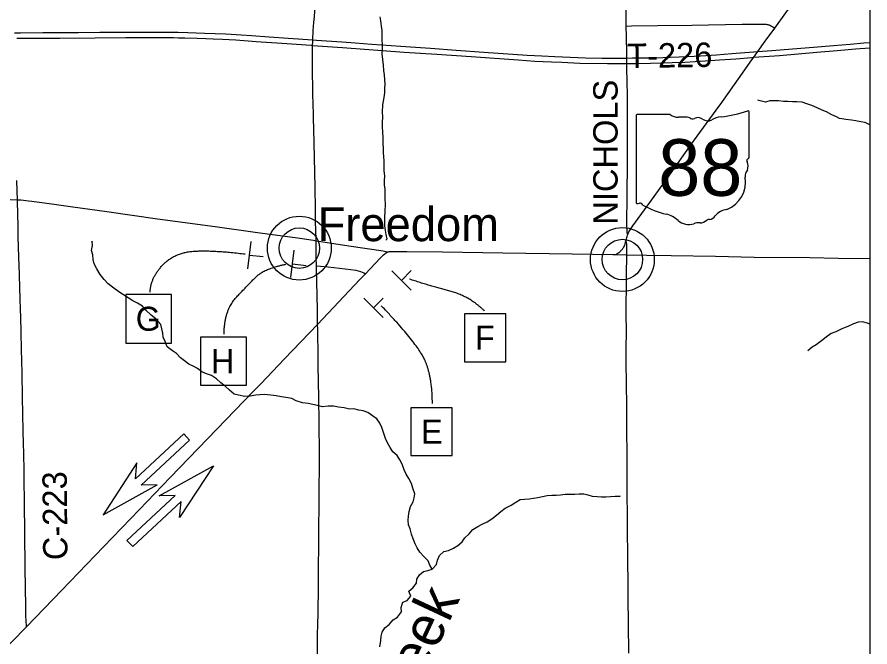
# Model space of a CAD drawing. Extents: x 0 to 34, y 0 to 22.
# Drawn here: x 13.701 to 18.671, y 14.409 to 18.077 of the extents above; entities that cross this region are included whole.
import ezdxf

# ---------------------------------------------------------------- set-up
doc = ezdxf.new("R2010")
doc.units = 0
for name, color, linetype in [('GM_X_County_Road', 7, 'Continuous'), ('GM_X_County_Road_Text', 7, 'Continuous'), ('GM_X_Interstate_Route', 7, 'Continuous'), ('GM_X_Minor_River', 7, 'Continuous'), ('GM_X_Minor_River_Text', 7, 'Continuous'), ('GM_X_State_Location', 7, 'Continuous'), ('GM_X_State_Route', 7, 'Continuous'), ('GM_X_State_Shield', 7, 'Continuous'), ('GM_X_Township_Road', 7, 'Continuous'), ('GM_X_Township_Road_Text', 7, 'Continuous'), ('GM_X_Unincorporated', 7, 'Continuous'), ('GM_X_Unincorporated_Location', 7, 'Continuous'), ('GM_X_Unincorporated_Text', 7, 'Continuous'), ('PM_P_Cells', 7, 'Continuous'), ('SH_Text', 7, 'Continuous'), ('SN_P_Signs', 7, 'Continuous')]:
    doc.layers.add(name, color=color, linetype=linetype)

msp = doc.modelspace()

# ---------------------------------------------------------------- linework, layer by layer
at = {"layer": 'GM_X_County_Road'}
for points in [[(17.2512, 18.0254), (17.2505, 18.0622), (17.2503, 18.1617)], [(17.2605, 16.8112), (17.2591, 16.8136), (17.258, 16.8161), (17.2571, 16.8198), (17.2565, 16.8243), (17.2557, 16.8355), (17.2554, 16.8677), (17.2554, 16.9284), (17.256, 16.9826), (17.2567, 17.0541), (17.2569, 17.1007), (17.2577, 17.1691), (17.2583, 17.2406), (17.2582, 17.3074), (17.259, 17.382), (17.2585, 17.4737), (17.258, 17.5545), (17.2574, 17.6089), (17.256, 17.7143), (17.2554, 17.7656), (17.2551, 17.8077), (17.2545, 17.8386), (17.2541, 17.8604), (17.2519, 17.9706), (17.2513, 18.0188), (17.2512, 18.0254)], [(13.7026, 17.0131), (13.7009, 17.0659), (13.6992, 17.1249)], [(13.7555, 14.5258), (13.7539, 14.5643), (13.7529, 14.5876), (13.7515, 14.6529), (13.7505, 14.7477), (13.7483, 14.8782), (13.748, 14.9419), (13.747, 15.0009), (13.746, 15.0987), (13.7441, 15.2214), (13.7437, 15.2789), (13.7422, 15.3565), (13.7414, 15.4342), (13.7394, 15.5351), (13.7383, 15.5942), (13.7367, 15.6656), (13.7347, 15.7666), (13.7329, 15.8629), (13.7297, 16.0027), (13.7271, 16.144), (13.7251, 16.2397), (13.7221, 16.3314), (13.7209, 16.3733), (13.7186, 16.4385), (13.7168, 16.4991), (13.7152, 16.5798), (13.7113, 16.6792), (13.708, 16.7973), (13.7067, 16.8703), (13.7047, 16.9215), (13.7026, 17.0131)], [(17.2492, 16.7724), (17.2511, 16.779), (17.2548, 16.793), (17.2569, 16.8003), (17.2592, 16.8077), (17.2605, 16.8112)], [(17.2539, 16.6935), (17.2541, 16.7174), (17.254, 16.7445), (17.2536, 16.7571), (17.2532, 16.7615), (17.2521, 16.7658), (17.2508, 16.7694), (17.2492, 16.7724)], [(17.2662, 14.3722), (17.2658, 14.4187), (17.2654, 14.4436), (17.265, 14.4747), (17.2651, 14.5197), (17.2638, 14.5895), (17.2637, 14.6003), (17.2631, 14.6407), (17.2626, 14.6794), (17.2618, 14.7166), (17.2614, 14.7599), (17.2615, 14.8277), (17.2612, 14.8649), (17.2609, 14.8913), (17.26, 14.9876), (17.259, 15.042), (17.2586, 15.0683), (17.2584, 15.1428), (17.2581, 15.1909), (17.2576, 15.2142), (17.2572, 15.2593), (17.2569, 15.3386), (17.2562, 15.4147), (17.2556, 15.4691), (17.2555, 15.5561), (17.255, 15.6447), (17.255, 15.7037), (17.2547, 15.7457), (17.2545, 15.8234), (17.2527, 15.932), (17.2518, 15.994), (17.2515, 16.0174), (17.2515, 16.0809), (17.2514, 16.1628), (17.2524, 16.23), (17.2511, 16.3648), (17.2511, 16.4067), (17.2521, 16.5), (17.2522, 16.5497), (17.2523, 16.6057), (17.2535, 16.6614), (17.2535, 16.6749), (17.2539, 16.6935)], [(15.4512, 14.3501), (15.4524, 14.4268), (15.4525, 14.4802), (15.4545, 14.5423), (15.456, 14.6012), (15.4564, 14.6587), (15.4566, 14.7099), (15.4571, 14.7783), (15.4581, 14.8264), (15.4585, 14.9056), (15.459, 14.9662), (15.4594, 14.9926), (15.4604, 15.0577), (15.4604, 15.0965), (15.4602, 15.1183), (15.4618, 15.2146), (15.4619, 15.269), (15.4621, 15.3218), (15.4624, 15.3545), (15.4629, 15.4336), (15.4634, 15.4771), (15.4636, 15.5376), (15.4632, 15.592), (15.4623, 15.6588), (15.4612, 15.7131), (15.4605, 15.7597), (15.4599, 15.8172), (15.4587, 15.8855), (15.4579, 15.9306), (15.457, 15.9694), (15.4565, 16.0331), (15.4555, 16.1201), (15.454, 16.233), (15.4532, 16.2601), (15.4521, 16.2873)]]:
    msp.add_lwpolyline(points, dxfattribs=at)
at = {"layer": 'GM_X_Interstate_Route'}
for points in [[(13.6852, 17.9863), (13.7215, 17.9865), (13.8507, 17.9874), (13.985, 17.9878), (14.0594, 17.9882), (14.1831, 17.9889), (14.3769, 17.9902), (14.4288, 17.9905), (14.4793, 17.9905), (14.5667, 17.99), (14.6399, 17.9887), (14.6967, 17.9876), (14.7928, 17.9844), (14.8558, 17.9821), (14.9156, 17.9792), (14.9495, 17.9772), (15.0062, 17.974), (15.0676, 17.9693), (15.1701, 17.9621), (15.2812, 17.9544), (15.4244, 17.9442), (15.4457, 17.9427), (15.5926, 17.9324), (15.6717, 17.9268), (15.7679, 17.9201), (15.9372, 17.9083), (16.0219, 17.9024), (16.1109, 17.8963), (16.2594, 17.8856), (16.4212, 17.8737), (16.6732, 17.8562), (16.7592, 17.8512), (16.8351, 17.8475), (16.9245, 17.843), (17.0131, 17.8403), (17.1084, 17.8386), (17.2258, 17.8382), (17.2545, 17.8386), (17.288, 17.8392), (17.3585, 17.8394), (17.4211, 17.8408), (17.5066, 17.8435), (17.5601, 17.8455), (17.6106, 17.8474), (17.6831, 17.8521), (17.7776, 17.8584), (17.8666, 17.865), (18.0187, 17.877), (18.0986, 17.8832), (18.3656, 17.9041), (18.4593, 17.9122), (18.5569, 17.9205), (18.635, 17.9268), (18.6712, 17.9296)], [(13.7002, 17.9542), (13.8218, 17.9548), (13.9505, 17.9554), (14.1551, 17.9566), (14.3339, 17.9577), (14.4149, 17.958), (14.6123, 17.9579), (14.6418, 17.9571), (14.6777, 17.9563), (14.7508, 17.9542), (14.8016, 17.9526), (14.8432, 17.9509), (14.8989, 17.9485), (14.9751, 17.944), (15.0937, 17.9355), (15.2443, 17.9247), (15.4155, 17.9131)], [(15.4155, 17.9131), (15.4231, 17.9126), (15.597, 17.9009), (15.9577, 17.874), (16.1462, 17.8611), (16.348, 17.8476), (16.622, 17.8281), (16.7181, 17.8216), (16.8149, 17.8161), (16.8751, 17.8139), (16.9808, 17.8098), (17.1422, 17.8073), (17.2375, 17.8076), (17.2551, 17.8077), (17.3226, 17.808), (17.4627, 17.8113), (17.5192, 17.8127), (17.5926, 17.8154), (17.6519, 17.8188), (17.71, 17.8221), (17.7947, 17.8277), (17.8896, 17.8351), (17.9818, 17.8421)], [(17.9818, 17.8421), (17.9942, 17.843), (18.1435, 17.8543), (18.3622, 17.8736), (18.481, 17.8831), (18.5867, 17.8916), (18.6712, 17.8983)]]:
    msp.add_lwpolyline(points, dxfattribs=at)
at = {"layer": 'GM_X_Minor_River'}
for points in [[(15.8152, 18.0783), (15.8183, 18.0546), (15.8224, 18.0252), (15.8265, 17.9996), (15.8258, 17.9721), (15.8261, 17.9455), (15.8293, 17.918), (15.8286, 17.8943), (15.8261, 17.8639), (15.8312, 17.8297), (15.8335, 17.7975), (15.8357, 17.7671), (15.8407, 17.7406), (15.842, 17.7121), (15.8432, 17.6865), (15.8425, 17.6618), (15.8428, 17.6362), (15.8374, 17.6086), (15.8303, 17.5658), (15.8289, 17.5231), (15.8302, 17.4955), (15.8286, 17.4632), (15.828, 17.4376), (15.8311, 17.4073), (15.8334, 17.374), (15.8328, 17.3389), (15.8341, 17.3133), (15.8353, 17.2886), (15.8356, 17.2639), (15.8377, 17.2393), (15.839, 17.2146), (15.8374, 17.1823), (15.8425, 17.152), (15.84, 17.1244), (15.8412, 17.0998), (15.8433, 17.0751), (15.8436, 17.0485), (15.8449, 17.0191), (15.8462, 16.9887), (15.8438, 16.945), (15.8423, 16.9118), (15.8416, 16.888), (15.8419, 16.8624), (15.846, 16.8349), (15.8491, 16.8112), (15.8551, 16.7847), (15.8504, 16.779)], [(18.4757, 17.4968), (18.45, 17.5088), (18.4186, 17.5246), (18.3929, 17.5348), (18.3634, 17.5487), (18.3329, 17.5616), (18.3035, 17.5727), (18.2759, 17.5809), (18.2456, 17.5843), (18.22, 17.584), (18.1935, 17.5866), (18.167, 17.5863), (18.1385, 17.5897), (18.0874, 17.5891), (18.0629, 17.5822), (18.0315, 17.5894), (18.0173, 17.594)], [(18.6436, 17.4634), (18.6189, 17.4669), (18.5894, 17.4723), (18.5628, 17.4768), (18.5314, 17.4812), (18.5075, 17.4842), (18.4932, 17.4869), (18.4757, 17.4968)], [(18.6712, 17.4496), (18.6703, 17.4503), (18.6436, 17.4634)], [(14.1407, 16.7468), (14.1386, 16.7714), (14.1386, 16.7695)], [(16.1207, 14.8614), (16.1062, 14.8859), (16.0964, 14.9115), (16.0725, 14.934), (16.0486, 14.9603), (16.0322, 14.9857), (16.0205, 15.0103), (16.0098, 15.0396), (16, 15.066), (15.9921, 15.0963), (15.9814, 15.1209), (15.9793, 15.1465), (15.9818, 15.1712), (15.9853, 15.1978), (15.9935, 15.2274), (16.0084, 15.2541), (16.0147, 15.2779), (16.0183, 15.3017), (16.0065, 15.3339), (15.9996, 15.3604), (15.9832, 15.3896), (15.9687, 15.4151), (15.9561, 15.4406), (15.9444, 15.4727), (15.9318, 15.4991), (15.9154, 15.5236), (15.8915, 15.5452), (15.8752, 15.5706), (15.8597, 15.597), (15.8471, 15.6235), (15.8392, 15.6519), (15.8265, 15.6878), (15.8158, 15.7124), (15.7976, 15.7378), (15.7718, 15.7555), (15.746, 15.7742), (15.7185, 15.7834), (15.6928, 15.7878), (15.6625, 15.7951), (15.6379, 15.7938), (15.6065, 15.8011), (15.5743, 15.8064), (15.5458, 15.8108), (15.5146, 15.8105), (15.4805, 15.8072), (15.452, 15.8154), (15.4245, 15.8218), (15.3979, 15.8271), (15.3648, 15.8315), (15.3277, 15.8434), (15.3029, 15.8555), (15.2783, 15.859), (15.2422, 15.8662), (15.21, 15.8715), (15.1806, 15.8759), (15.1408, 15.8802), (15.1162, 15.878), (15.0916, 15.8748), (15.0585, 15.8688), (15.0292, 15.8684), (14.9922, 15.8746), (14.9656, 15.8819), (14.9398, 15.9044), (14.9139, 15.9288), (14.8882, 15.9465), (14.8623, 15.9709), (14.8347, 15.9896), (14.8052, 15.9997), (14.7776, 16.0117), (14.7518, 16.0304), (14.727, 16.0453), (14.7014, 16.0564), (14.6775, 16.0751), (14.6526, 16.0938), (14.6306, 16.1182), (14.6058, 16.1331), (14.5762, 16.1575), (14.5635, 16.1887), (14.5529, 16.2132), (14.5498, 16.2369), (14.5447, 16.2616), (14.5378, 16.2862), (14.5091, 16.32), (14.4823, 16.3406), (14.4508, 16.3696), (14.4315, 16.3941), (14.403, 16.4109), (14.3753, 16.4248), (14.3486, 16.4425), (14.321, 16.4593), (14.2943, 16.477), (14.2656, 16.4985), (14.2322, 16.5247), (14.2083, 16.5482), (14.1852, 16.5773), (14.165, 16.6103), (14.1495, 16.6396), (14.1435, 16.6651), (14.1432, 16.6927), (14.1354, 16.7173), (14.1407, 16.7468)], [(18.5068, 16.2626), (18.4715, 16.2445), (18.4451, 16.2347), (18.416, 16.2125), (18.3898, 16.1913), (18.3588, 16.1691), (18.3343, 16.1555), (18.309, 16.1334), (18.3099, 16.1334)], [(18.6712, 16.2887), (18.6574, 16.2945), (18.6269, 16.3018), (18.6032, 16.3006), (18.5749, 16.2908), (18.5427, 16.2762), (18.5172, 16.2665), (18.5068, 16.2626)], [(15.8151, 14.4088), (15.8204, 14.4459), (15.822, 14.4716), (15.8293, 14.4954), (15.8442, 14.5202), (15.8686, 14.5404), (15.8919, 14.5673), (15.9183, 14.5828), (15.9407, 14.6134), (15.9395, 14.6381), (15.9486, 14.6695), (15.974, 14.6803), (15.9955, 14.7043), (15.9838, 14.7336), (16.0082, 14.7528), (16.0288, 14.7806), (16.0313, 14.8044), (16.0453, 14.8283), (16.0697, 14.8485), (16.0952, 14.8545), (16.1207, 14.8614), (16.145, 14.8883), (16.1513, 14.914), (16.1624, 14.9426), (16.1877, 14.9647), (16.216, 14.9708), (16.2452, 14.9844), (16.2697, 15.0008), (16.2941, 15.021), (16.3108, 15.045), (16.3362, 15.0681), (16.3576, 15.0939), (16.3859, 15.1114), (16.4122, 15.125), (16.4414, 15.1386), (16.4677, 15.156), (16.494, 15.1772), (16.5203, 15.1974), (16.5447, 15.2176), (16.5805, 15.2351), (16.6068, 15.2525), (16.6331, 15.268), (16.6587, 15.2702), (16.6852, 15.2715), (16.7098, 15.2756), (16.7362, 15.2797), (16.7636, 15.2847), (16.7901, 15.2907), (16.8175, 15.293), (16.8421, 15.2932), (16.8677, 15.2945), (16.8951, 15.2986), (16.9509, 15.2993), (16.9774, 15.3015), (17.003, 15.3008), (17.0267, 15.2944), (17.0533, 15.2871), (17.0808, 15.2846), (17.1064, 15.283), (17.1329, 15.2833), (17.1585, 15.2846), (17.1868, 15.2877), (17.2134, 15.2871), (17.2171, 15.289)]]:
    msp.add_lwpolyline(points, dxfattribs=at)
at = {"layer": 'GM_X_State_Route'}
for points in [[(15.4253, 17.6106), (15.4249, 17.6255), (15.4244, 17.6845), (15.4231, 17.7357), (15.4222, 17.7932), (15.4218, 17.8414), (15.4221, 17.885), (15.4231, 17.9126), (15.4238, 17.9332), (15.4244, 17.9442), (15.4272, 18), (15.4305, 18.0465), (15.4338, 18.0806), (15.437, 18.1115), (15.4405, 18.1471), (15.4466, 18.198), (15.4511, 18.2303), (15.4581, 18.2764), (15.4671, 18.338), (15.4675, 18.3404)], [(17.9736, 17.8144), (17.9942, 17.843), (18.0187, 17.877), (18.0616, 17.9363), (18.1166, 18.0127), (18.1805, 18.1014), (18.2511, 18.1988)], [(17.7976, 17.5666), (17.9278, 17.7511), (17.9736, 17.8144)], [(15.4521, 16.2873), (15.4519, 16.3052), (15.451, 16.3857), (15.449, 16.4416), (15.4472, 16.5489), (15.4459, 16.597), (15.4452, 16.6282), (15.4441, 16.6794), (15.4432, 16.7751), (15.4418, 16.8425), (15.4406, 16.8782), (15.44, 16.9559), (15.4372, 17.088), (15.4363, 17.172), (15.4317, 17.3443), (15.4278, 17.4941), (15.4259, 17.5882), (15.4253, 17.6106)], [(17.2605, 16.8112), (17.2625, 16.8162), (17.2647, 16.8211), (17.267, 16.8259), (17.2704, 16.832), (17.2739, 16.8378), (17.2902, 16.8623), (17.372, 16.9757), (17.4893, 17.1382), (17.6439, 17.3544), (17.7961, 17.5646), (17.7976, 17.5666)], [(13.6208, 17.016), (13.7026, 17.0131), (13.7234, 17.0123), (13.7389, 17.0111), (13.7529, 17.0098), (13.7683, 17.008), (13.7868, 17.0056), (13.9176, 16.9878), (14.0265, 16.9723), (14.2234, 16.9445), (14.5198, 16.9028), (14.8555, 16.8569), (15.088, 16.8257), (15.3342, 16.7908), (15.428, 16.7773), (15.4432, 16.7751), (15.4457, 16.7747)], [(17.2492, 16.7724), (17.2511, 16.779), (17.2548, 16.793), (17.2569, 16.8003), (17.2592, 16.8077), (17.2605, 16.8112)], [(15.4457, 16.7747), (15.6348, 16.7456), (15.8342, 16.7157), (15.8428, 16.7141), (15.8497, 16.7121), (15.8578, 16.7086)], [(17.1901, 16.6946), (17.208, 16.7063), (17.212, 16.7092), (17.2153, 16.7121), (17.2188, 16.7156), (17.222, 16.719), (17.2255, 16.7227), (17.2287, 16.7266), (17.2314, 16.7304), (17.2335, 16.7339), (17.236, 16.7382), (17.2402, 16.7467), (17.2438, 16.7554), (17.2474, 16.7659), (17.2492, 16.7724)], [(15.4521, 16.2873), (15.6985, 16.5482), (15.7305, 16.5816), (15.8177, 16.6729), (15.8368, 16.692), (15.8442, 16.699), (15.848, 16.702), (15.8521, 16.7051), (15.8578, 16.7086)], [(15.8578, 16.7086), (15.8618, 16.7099), (15.8657, 16.7108), (15.8702, 16.7115), (15.8757, 16.7121), (15.8796, 16.7123), (15.8841, 16.7125), (15.9716, 16.7122), (16.18, 16.7098), (16.5312, 16.7045), (16.9368, 16.6988), (17.173, 16.6951), (17.1901, 16.6946)], [(17.1901, 16.6946), (17.2539, 16.6935), (17.3711, 16.6915), (17.5125, 16.6884), (17.7719, 16.6845), (17.9957, 16.6799), (18.3219, 16.6765), (18.4866, 16.6743), (18.6712, 16.6713)], [(15.1208, 15.9421), (15.2595, 16.0864), (15.4521, 16.2873)], [(13.4993, 14.2609), (13.671, 14.4383), (13.7555, 14.5258), (13.9625, 14.7401), (14.2036, 14.9913), (14.4144, 15.2089), (14.5928, 15.3952), (14.8657, 15.678), (15.0774, 15.897), (15.1208, 15.9421)]]:
    msp.add_lwpolyline(points, dxfattribs=at)
at = {"layer": 'GM_X_State_Shield'}
for p, q in [((17.308, 17.5015), (17.308, 17.0012)), ((17.5075, 17.5101), (17.3145, 17.5101)), ((17.9671, 17.2607), (17.9671, 17.5225)), ((17.9671, 17.2608), (17.9671, 17.2607))]:
    msp.add_line(p, q, dxfattribs=at)
for centre, radius, start, end in [((17.3155, 17.5025), 0.00764, 98.1301, 188.1301), ((17.5535, 17.5681), 0.0741, 231.6195, 271.1119), ((17.8215, 17.3573), 0.1406, 97.3462, 120.7689), ((17.7323, 18.1921), 0.699, 275.8445, 288.9065), ((17.9598, 17.5235), 0.00734, 351.8621, 97.738), ((17.578, 17.2292), 0.2659, 80.4867, 94.9883), ((17.6384, 17.5051), 0.0214, 219.7921, 297.1024), ((17.6698, 17.4473), 0.0444, 54.4667, 119.1411), ((17.7271, 17.5266), 0.0534, 233.8562, 294.8282), ((17.9654, 17.2415), 0.0114, 107.944, 210.337), ((17.9593, 17.2597), 0.00785, 289.6038, 7.7341), ((17.8932, 17.2084), 0.0682, 340.033, 23.6496), ((17.9934, 17.1512), 0.0496, 136.8065, 186.9296), ((17.7715, 17.1179), 0.1748, 292.3089, 8.9858), ((17.3156, 17.0001), 0.0077, 171.9584, 258.3066), ((17.3168, 17.0512), 0.0588, 267.339, 280.6039), ((17.3288, 16.9723), 0.0212, 29.7484, 93.2717), ((17.5964, 17.4218), 0.5048, 240.4129, 257.1985), ((17.8452, 16.8607), 0.0958, 94.4031, 142.5768), ((17.4459, 16.7764), 0.1579, 47.1842, 75.836), ((17.7239, 16.9527), 0.0565, 282.8732, 323.2771), ((17.6168, 16.9698), 0.1002, 230.7004, 286.2918), ((17.6747, 16.7968), 0.0824, 85.6951, 111.2099), ((17.682, 16.9323), 0.0534, 268.777, 315.5493), ((17.7303, 16.8839), 0.015, 65.7517, 132.6484)]:
    msp.add_arc(centre, radius, start, end, dxfattribs=at)
at = {"layer": 'GM_X_Township_Road'}
for points in [[(17.2512, 18.0254), (17.2807, 18.0259), (17.4331, 18.0283), (17.6324, 18.0303), (17.9261, 18.036), (18.0522, 18.0363), (18.0631, 18.036), (18.0674, 18.0356), (18.0714, 18.0351), (18.0756, 18.0342), (18.0797, 18.0331), (18.0834, 18.032), (18.0873, 18.0306), (18.0909, 18.029), (18.098, 18.0252), (18.1046, 18.0208), (18.1166, 18.0127)], [(15.4452, 16.6282), (15.4683, 16.6264), (15.5134, 16.6229), (15.58, 16.6155), (15.6464, 16.6069), (15.6742, 16.6029), (15.6896, 16.5998), (15.7018, 16.5964), (15.7122, 16.5926), (15.7215, 16.5878), (15.7305, 16.5816)]]:
    msp.add_lwpolyline(points, dxfattribs=at)
at = {"layer": 'GM_X_Unincorporated'}
for centre, radius in [((15.3458, 16.7318), 0.186), ((17.2287, 16.6653), 0.186), ((15.3458, 16.7318), 0.1179), ((17.2287, 16.6653), 0.1179)]:
    msp.add_circle(centre, radius, dxfattribs=at)
at = {"layer": 'GM_X_Unincorporated_Location'}
for p, q in [((15.3458, 16.7318), (15.3458, 16.7318)), ((17.2287, 16.6653), (17.2287, 16.6653))]:
    msp.add_line(p, q, dxfattribs=at)
at = {"layer": 'PM_P_Cells'}
for p, q in [((14.6725, 15.6497), (14.3905, 15.3874)), ((14.4246, 15.3508), (14.7065, 15.613)), ((14.7065, 15.613), (14.6725, 15.6497)), ((14.6895, 15.6314), (14.6895, 15.6314)), ((14.3997, 15.4804), (14.2025, 15.1784)), ((14.3905, 15.3874), (14.3997, 15.4804)), ((14.5294, 15.2896), (14.8448, 15.4644)), ((14.8448, 15.4644), (14.6476, 15.1625)), ((14.8448, 15.4644), (14.8448, 15.4644)), ((14.2025, 15.1784), (14.5179, 15.3533)), ((14.5179, 15.3533), (14.4246, 15.3508)), ((14.3408, 15.0298), (14.6227, 15.292)), ((14.6227, 15.292), (14.5294, 15.2896)), ((14.6568, 15.2554), (14.3749, 14.9932)), ((14.6476, 15.1625), (14.6568, 15.2554)), ((14.2025, 15.1784), (14.2025, 15.1784)), ((14.3749, 14.9932), (14.3408, 15.0298)), ((14.3578, 15.0115), (14.3578, 15.0115))]:
    msp.add_line(p, q, dxfattribs=at)
at = {"layer": 'SH_Text'}
for points in [[(1.6712, 21.2991), (18.6712, 21.2991), (18.6712, 4.2991), (1.6712, 4.2991)], [(14.3344, 16.1784), (14.6003, 16.1784), (14.6003, 16.4617), (14.3344, 16.4617)], [(16.309, 16.0692), (16.5485, 16.0692), (16.5485, 16.3492), (16.309, 16.3492)], [(14.7696, 15.9328), (15.0371, 15.9328), (15.0371, 16.2134), (14.7696, 16.2134)], [(15.9953, 15.5232), (16.2375, 15.5232), (16.2375, 15.8025), (15.9953, 15.8025)]]:
    msp.add_lwpolyline(points, close=True, dxfattribs=at)
for points in [[(14.4768, 16.4756), (14.4768, 16.5515), (14.6115, 16.7034), (14.8315, 16.7224), (15.0307, 16.6977)], [(14.9074, 16.2307), (14.9074, 16.3693), (15.0516, 16.5231), (15.1426, 16.6123), (15.2673, 16.6381)], [(16.4254, 16.3652), (16.3362, 16.4525), (16.1086, 16.5114), (15.9872, 16.5512)], [(16.1211, 15.8268), (16.1211, 15.9763), (16.0381, 16.1723), (15.8232, 16.3963)]]:
    msp.add_open_spline(points, degree=2, dxfattribs=at)
at = {"layer": 'SN_P_Signs'}
for p, q in [((15.0462, 16.6121), (15.0645, 16.771)), ((15.2966, 16.5608), (15.3149, 16.7197)), ((15.0553, 16.6915), (15.1348, 16.6824)), ((15.3057, 16.6403), (15.3852, 16.6311)), ((15.9979, 16.4876), (15.8842, 16.6001)), ((15.9411, 16.5438), (15.9973, 16.6007)), ((15.8353, 16.3281), (15.7215, 16.4406)), ((15.7784, 16.3844), (15.8346, 16.4412))]:
    msp.add_line(p, q, dxfattribs=at)

# ---------------------------------------------------------------- texts
at = {"layer": 'GM_X_County_Road_Text'}
for s, rotation, p in [('NICHOLS', 90, (17.2008, 16.8683)), ('C-223', 90.5521, (13.9952, 14.9152))]:
    msp.add_text(s, height=0.14205, rotation=rotation, dxfattribs=at).set_placement(p)
at = {"layer": 'GM_X_Minor_River_Text'}
msp.add_text('Creek', height=0.23688, rotation=64.9784, dxfattribs=at).set_placement((15.9263, 13.924))
at = {"layer": 'GM_X_State_Location'}
for s in ['s', 'r']:
    msp.add_text(s, height=0.000473, dxfattribs=at).set_placement((17.6301, 17.218))
msp.add_text('88', height=0.000473, rotation=0, dxfattribs=at).set_placement((17.5109, 17.1836))
at = {"layer": 'GM_X_State_Shield'}
msp.add_text('88', height=0.32959, dxfattribs=at).set_placement((17.4373, 17.0364))
at = {"layer": 'GM_X_Township_Road_Text'}
msp.add_text('T-226', height=0.14205, rotation=0.8531, dxfattribs=at).set_placement((17.2575, 17.7801))
at = {"layer": 'GM_X_Unincorporated_Text'}
msp.add_text('Freedom', height=0.19744, rotation=0, dxfattribs=at).set_placement((15.4526, 16.7724))
at = {"layer": 'SH_Text'}
for s, p in [('G', (14.3925, 16.2504)), ('F', (16.3702, 16.1399)), ('H', (14.8308, 16.0034)), ('E', (16.0558, 15.5932))]:
    msp.add_text(s, height=0.14, dxfattribs=at).set_placement(p)

doc.saveas('drawing.dxf')
